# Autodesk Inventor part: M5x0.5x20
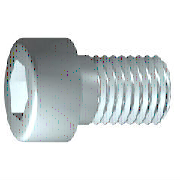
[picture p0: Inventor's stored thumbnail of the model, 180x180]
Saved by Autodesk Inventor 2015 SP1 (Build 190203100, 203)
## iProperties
IsCustomPart: 0
Created: 2009-02
Part Number: M5x0.5x20
Material: Steel, Mild
Description: 6각머리 태핑 나사
Document SubType Name: Modeling
Standard: KS B 1003
Designer: SeoGD™
Standards Organization: KS
Language: ko-KR
Size Designation: M 5 x 20
Categories: <MemberInstance><Categories><Category DisplayName="조임쇠" InternalName="e4da775c-781d-43d5-af7c-5136215cf5a6" Mnemonic="FSTN"><Category DisplayName="볼트" InternalN
Density: 7.86 g/cm^3
Appearance: Metal-Steel
Mass: 4.9629 g
Surface Area: 5.88237 cm^2
Volume: 0.631412 cm^3
Author: SeoGD™
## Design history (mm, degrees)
sketch "스케치1"
  geometry: L1 (-1.167, 0)-(20, 0); L2 (20, 0)-(20, 2.5); L3 (20, 2.5)-(2, 2.5); L4 (2, 2.5)-(1.509, 2.5); L5 (1.509, 2.5)-(0, 2.5); L6 (0, 2.5)-(0, 4.25); L7 (0, 4.25)-(-5, 4.25); L8 (-5, 4.25)-(-5, 2.309); L9 (-5, 2.309)-(-2.5, 2.309); L10 (-2.5, 2.309)-(-1.167, 0); L11 (-10, 0)-(25, 0) reference; L12 (0, -0.85)-(0, 5.1) reference; L13 (2, 2.5)-(0, 2.5)
  constraints: 22 end point, 6 parallel, 2 collinear, 2 perpendicular, 1 horizontal, 1 point on line
  dimensions: "d1" = 18 distance from line of L3.end L2 (= GEL); "d2" = 0.49086 distance of L4.end L3.end (computed from GAL); "d3" = 5 distance between parallel lines of L8 L6 (= KOH); "d4" = 2.5 distance of L8.end L9.end (= INTI); "d5" = 60 deg angle of L10 L1; "d6" = 5 diameter of L3 L1 (= GD); "d7" = 5 diameter of L5 L1 (= BDM); "d8" = 4.6188 diameter of L9 L1 (= 1.1547 x SW); "d9" = 8.5 diameter of L7 L1 (= KOD); "d26" = 20 distance between parallel lines of L12 L2 (= NLG)
revolve "본체" sketch "스케치1" stored, may be unused: angle "d10" = 90 deg
sketch "스케치2"
  geometry: L1 (0, -5.95)-(0, 5.95) reference; L2 (-5.95, 0)-(5.95, 0) reference; L3 (2.309, 0)-(1.155, -2); L4 (1.155, -2)-(-1.155, -2); L5 (-1.155, -2)-(-2.309, 0); L6 (-2.309, 0)-(-1.155, 2); L7 (-1.155, 2)-(1.155, 2); L8 (1.155, 2)-(2.309, 0); 2 further points
  constraints: 12 end point, 1 coincident, 1 horizontal alignment, 1 point on line, 12 other
extrude "슬롯" join sketch "스케치2" stored distance "d11" = 10; taper "d12" = 0 deg
workplane "Work Plane1"
fillet "Fillet2" dims "d30" = 0.1 (= R)
body "Solid1"
fillet "모깎기1" dims "d17" = 0.5 (= RR)
feature "스레드" dims "d13" = 18 (= GEL), "d14" = 0
chamfer "모따기1" distance "d15" = 0.49076 (= -0.5 x SPD + 0.5 x GD); stored, may be unused: second distance "d16" = 0.49076 (= GUL), angle "d27" = 45 deg
other parameters: "GD" = 5 (= NND) [user parameter; used in 2 equation terms], "NLG" = 20 [user parameter; used in 1 equation term], "GEL" = 18 [user parameter; used in 2 equation terms], "KOD" = 8.5 [user parameter; used in 1 equation term], "KOH" = 5 [user parameter; used in 1 equation term], "INTI" = 2.5 [user parameter; used in 1 equation term], "GAL" = 0.49076 (= 0.61345 x PTC) [user parameter; used in 1 equation term], "GUL" = 0.49076 (= 0.61345 x PTC) [user parameter; used in 1 equation term], "BDM" = 5 (= NND) [user parameter; used in 1 equation term], "SW" = 4 [user parameter; used in 2 equation terms], "RR" = 0.5 [user parameter; used in 1 equation term], "SPD" = 4.01848 (= NND - 1.2269 x PTC) [user parameter; used in 1 equation term], "d19" = 0, "d28" = 0, "d29" = 0, "R" = 0.1 [user parameter; used in 1 equation term], "PHH" = 0.2 [user parameter], "GD1" = 4.01848 (= THREADDIA - 1.2269 x PTC) [user parameter], "THREADDIA" = 5 [user parameter; used in 1 equation term], "FAWI" = 45 deg [user parameter], "TPU" = 12.5 (computed from PTC) [user parameter], "PTC" = 0.8 [user parameter; used in 5 equation terms], "NND" = 5 [user parameter; used in 3 equation terms], "TOA" = 30 deg [user parameter], "E0" = 4.62 (= 1.155 x SW) [user parameter]
